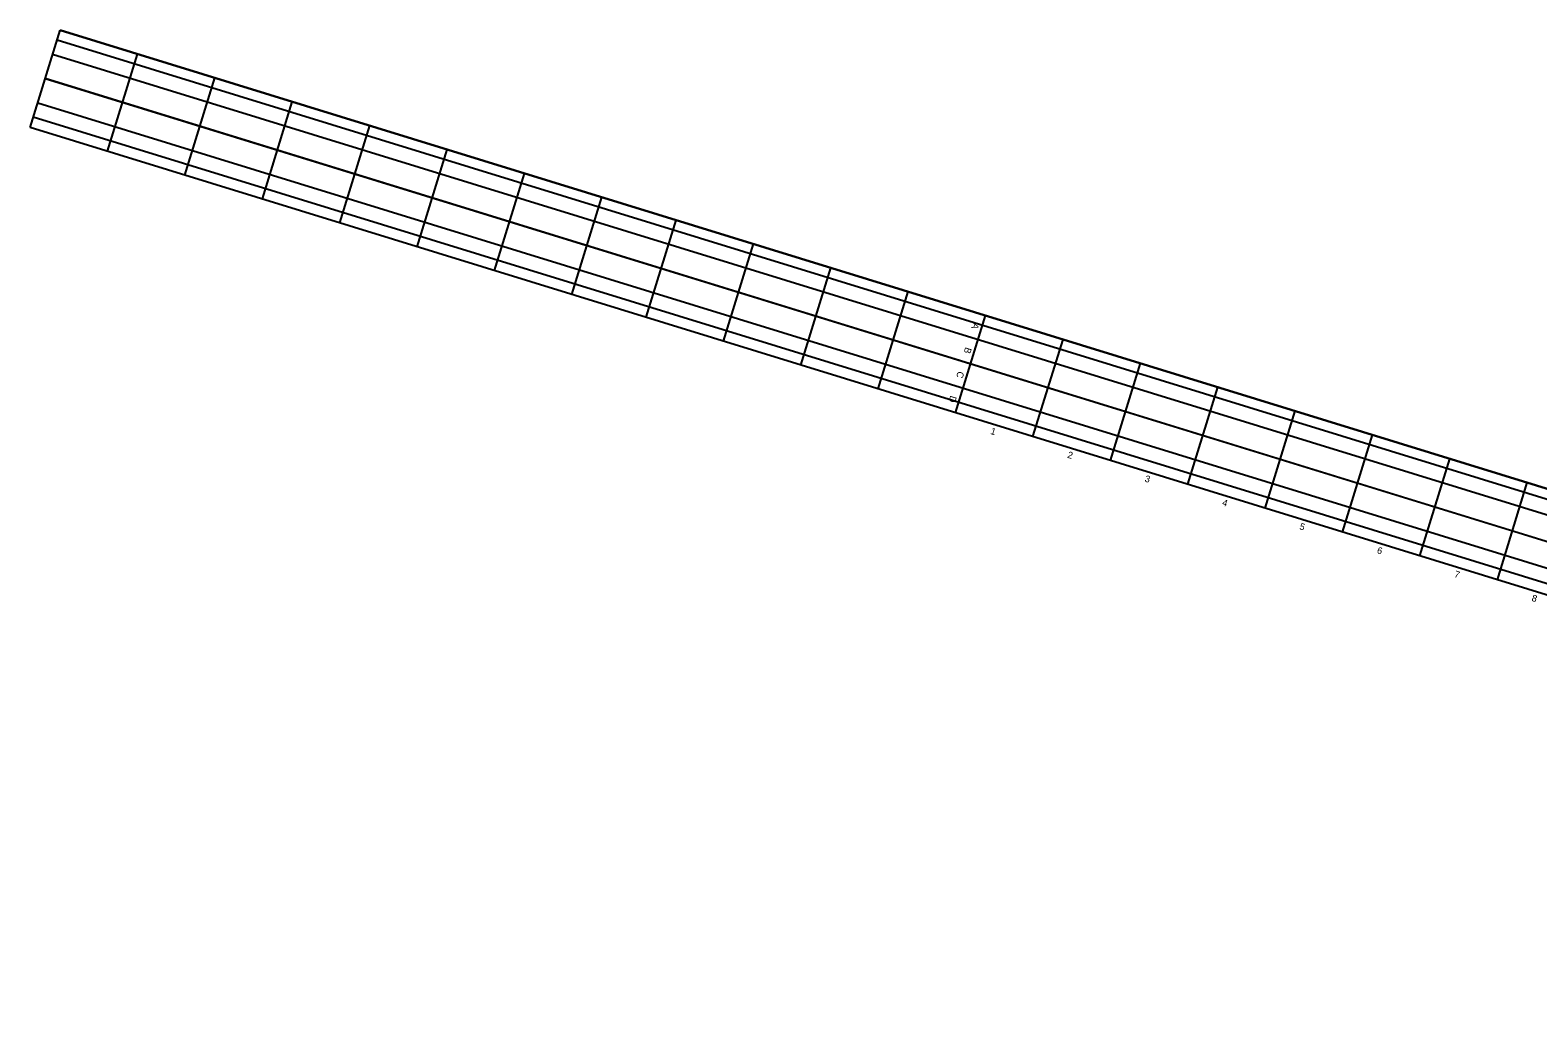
# Model space of a CAD drawing. Extents: x -886320 to -884760, y -1024172 to -1023483.
# Drawn here: x -886320.2 to -886095.9, y -1024049.7 to -1023900.9 of the extents above; entities that cross this region are included whole.
import ezdxf

# ---------------------------------------------------------------- set-up
doc = ezdxf.new("R2010")
doc.units = 0
for name, color, linetype in [('Stavajici_betonova_draha', 7, 'Continuous'), ('Stavajici_betonova_draha_Popis desky', 7, 'Continuous'), ('Stavajici_betonova_draha_Spára', 7, 'Continuous'), ('Stavajici_drahovy_system_TWY', 7, 'Continuous'), ('Stavajici_drahovy_system_TWY_osy', 7, 'Continuous')]:
    doc.layers.add(name, color=color, linetype=linetype)

msp = doc.modelspace()

# ---------------------------------------------------------------- linework, layer by layer
at = {"layer": 'Stavajici_betonova_draha'}
for p, q in [((-886315.74, -1023900.86), (-885865.51, -1024039.77)), ((-885884.75, -1024049.68), (-886320.21, -1023915.34))]:
    msp.add_line(p, q, dxfattribs=at)
at = {"layer": 'Stavajici_betonova_draha_Spára'}
for p, q in [((-886320.21, -1023915.34), (-886315.74, -1023900.86)), ((-885865.51, -1024039.77), (-886315.74, -1023900.86)), ((-885870.32, -1024042.24), (-886316.86, -1023904.48)), ((-886308.69, -1023918.89), (-886304.23, -1023904.42)), ((-885875.13, -1024044.72), (-886317.98, -1023908.1)), ((-886297.18, -1023922.44), (-886292.71, -1023907.97)), ((-885879.94, -1024047.2), (-886319.09, -1023911.72)), ((-886285.66, -1023925.99), (-886281.2, -1023911.52)), ((-886274.15, -1023929.54), (-886269.69, -1023915.07)), ((-885884.75, -1024049.68), (-886320.21, -1023915.34)), ((-886262.64, -1023933.1), (-886258.17, -1023918.63)), ((-886251.12, -1023936.65), (-886246.66, -1023922.18)), ((-886239.61, -1023940.2), (-886235.14, -1023925.73)), ((-886228.57, -1023943.61), (-886224.11, -1023929.13)), ((-886217.06, -1023947.16), (-886212.59, -1023932.69)), ((-886205.54, -1023950.71), (-886201.08, -1023936.24)), ((-886194.03, -1023954.26), (-886189.56, -1023939.79)), ((-886182.51, -1023957.82), (-886178.05, -1023943.34)), ((-886171, -1023961.37), (-886166.53, -1023946.9)), ((-886159.48, -1023964.92), (-886155.02, -1023950.45)), ((-886147.97, -1023968.47), (-886143.51, -1023954)), ((-886136.46, -1023972.02), (-886131.99, -1023957.55)), ((-886124.94, -1023975.58), (-886120.48, -1023961.11)), ((-886113.43, -1023979.13), (-886108.96, -1023964.66)), ((-886101.91, -1023982.68), (-886097.45, -1023968.21))]:
    msp.add_line(p, q, dxfattribs=at)
at = {"layer": 'Stavajici_drahovy_system_TWY'}
for p, q in [((-885887.27, -1024034.67), (-886316.2, -1023902.35)), ((-886077.8, -1023988.45), (-886319.74, -1023913.81))]:
    msp.add_line(p, q, dxfattribs=at)
at = {"layer": 'Stavajici_drahovy_system_TWY_osy'}
msp.add_line((-885886.7, -1024041.13), (-886317.97, -1023908.08), dxfattribs=at)

# ---------------------------------------------------------------- texts
at = {"layer": 'Stavajici_betonova_draha_Popis desky'}
for s, rotation, p in [('A', 252.8547, (-886179.93, -1023944.34)), ('B', 252.8547, (-886181.05, -1023947.99)), ('C', 252.8547, (-886182.16, -1023951.57)), ('D', 252.8547, (-886183.28, -1023955.2)), ('1', 342.8547, (-886177.4, -1023960.96)), ('2', 342.8547, (-886165.96, -1023964.49)), ('3', 342.8547, (-886154.45, -1023968.04)), ('4', 342.8547, (-886142.93, -1023971.6)), ('5', 342.8547, (-886131.42, -1023975.15)), ('6', 342.8547, (-886119.9, -1023978.7)), ('7', 342.8547, (-886108.39, -1023982.25)), ('8', 342.8547, (-886096.88, -1023985.8))]:
    msp.add_text(s, height=1, rotation=rotation, dxfattribs=at).set_placement(p)

doc.saveas('drawing.dxf')
